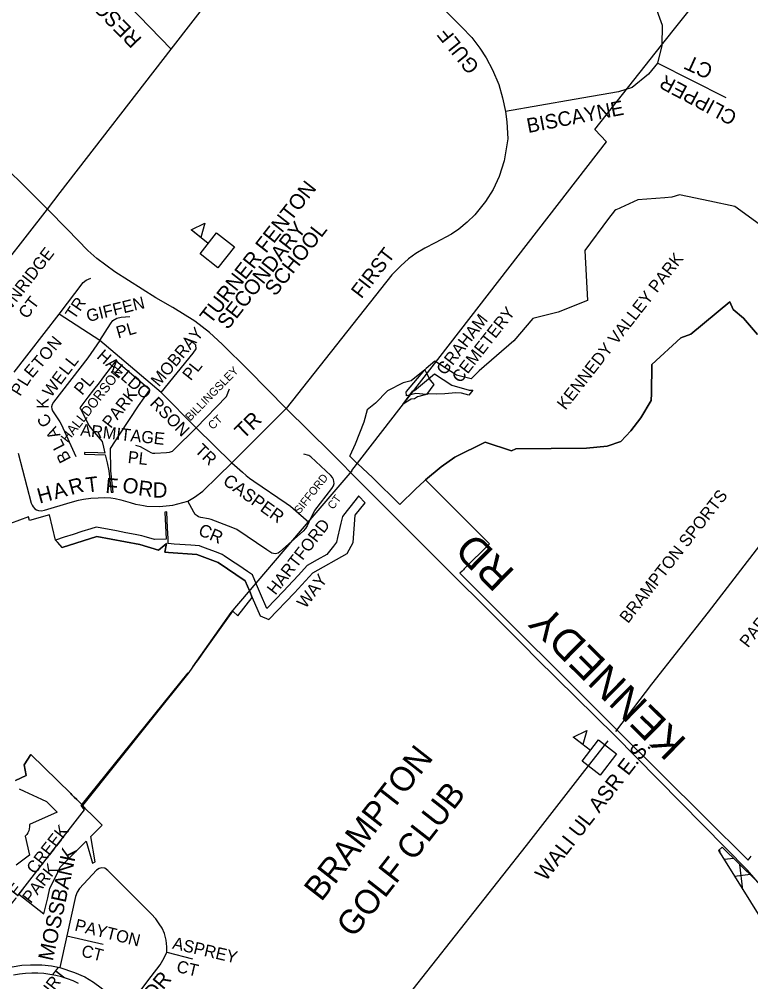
# Model space of a CAD drawing. Extents: x 586326 to 623965, y 4819854 to 4857850.
# Drawn here: x 602920 to 604127, y 4835364 to 4836952 of the extents above; entities that cross this region are included whole.
import ezdxf

# ---------------------------------------------------------------- set-up
doc = ezdxf.new("R2010")
doc.units = 0
for name, color, linetype in [('407 Parkway Belt', 7, 'Continuous'), ('Cemeteries', 7, 'Continuous'), ('Lots_Concessions', 7, 'Continuous'), ('Major Rds and Hwys', 7, 'Continuous'), ('Major Rds Lbls', 7, 'Continuous'), ('Minor Rd Lbls', 7, 'Continuous'), ('Minor Rds', 7, 'Continuous'), ('Park Lbls', 7, 'Continuous'), ('Park Outlines', 7, 'Continuous'), ('Proposed Secondary Rds', 7, 'Continuous'), ('Pts of Interest', 7, 'Continuous'), ('School Syms_Lbls', 7, 'Continuous')]:
    doc.layers.add(name, color=color, linetype=linetype)

msp = doc.modelspace()

# ---------------------------------------------------------------- linework, layer by layer
at = {"layer": '407 Parkway Belt'}
for p, q in [((604076.8, 4835576.2), (604076, 4835582.9)), ((604099.2, 4835568), (604083.2, 4835566)), ((604114.4, 4835516.1), (604109.2, 4835558.1)), ((604126.6, 4835541.1), (604100.7, 4835537.9))]:
    msp.add_line(p, q, dxfattribs=at)
msp.add_lwpolyline([(604440.3, 4835233.5), (604080.2, 4835586.6), (604073.8, 4835581), (604206.1, 4835369.5), (604182.1, 4835313.5)], dxfattribs=at)
at = {"layer": 'Cemeteries'}
for p, q in [((603572.2, 4836339.7), (603605.2, 4836367)), ((603605.2, 4836367), (603633.8, 4836348.7)), ((603633.8, 4836348.7), (603662.4, 4836340.4)), ((603552.9, 4836316.5), (603569.6, 4836339)), ((603566.7, 4836325.5), (603561.3, 4836322)), ((603572.2, 4836326.2), (603566.7, 4836325.5)), ((603569.6, 4836339), (603572.2, 4836339.7)), ((603577.3, 4836329.4), (603572.2, 4836326.2)), ((603595.9, 4836334.2), (603577.3, 4836329.4)), ((603608.4, 4836333.9), (603595.9, 4836334.2)), ((603622.5, 4836334.5), (603608.4, 4836333.9)), ((603640.8, 4836336.1), (603622.5, 4836334.5)), ((603649.8, 4836335.5), (603640.8, 4836336.1)), ((603661.9, 4836332.3), (603649.8, 4836335.5)), ((603668.6, 4836340.3), (603661.9, 4836332.3)), ((603662.4, 4836340.4), (603668.6, 4836340.3)), ((603561.3, 4836322), (603552.9, 4836316.5))]:
    msp.add_line(p, q, dxfattribs=at)
at = {"layer": 'Lots_Concessions'}
for p, q in [((603980, 4836909.2), (604121.5, 4837088.4)), ((603870.1, 4836770.5), (603980, 4836909.2)), ((603889.4, 4836749.9), (603870.1, 4836770.5)), ((603468.9, 4836207.8), (603889.4, 4836749.9)), ((603400.4, 4836126.6), (603469.6, 4836207)), ((603269.7, 4835973.6), (603400.4, 4836126.6)), ((604057.3, 4835974.1), (604147.8, 4836091.2)), ((603206.8, 4835884.2), (603269.7, 4835973.6)), ((603964.3, 4835855.3), (604057.3, 4835974.1)), ((603022.1, 4835655), (603199.1, 4835874.3)), ((603904.4, 4835777.3), (603964.3, 4835855.3)), ((603891.6, 4835761.9), (603852.8, 4835712.7)), ((603852.8, 4835712.7), (603756.4, 4835589.2)), ((602918.1, 4835507.5), (603028, 4835648.2)), ((603028, 4835648.2), (603022.1, 4835655)), ((603756.4, 4835589.2), (603561.5, 4835341.6))]:
    msp.add_line(p, q, dxfattribs=at)
at = {"layer": 'Major Rds and Hwys'}
for points in [[(603170.9, 4836903.1), (603308.5, 4837080.7)], [(603527.1, 4837063.6), (603650, 4836939.9), (603666.9, 4836922.3), (603680, 4836904.6), (603690.7, 4836888.4), (603701.2, 4836868.9), (603711.5, 4836844.6), (603717.8, 4836822.3), (603722.8, 4836799.8)], [(602966.9, 4836638.8), (602987.5, 4836666.2), (603170.9, 4836903.1)], [(603722.8, 4836799.8), (603725, 4836782.9), (603726.5, 4836754.8), (603720.4, 4836718.4), (603712.1, 4836692.7), (603702.2, 4836671.1), (603689.8, 4836651.3), (603672.1, 4836629.7), (603659.2, 4836617.4), (603645.5, 4836606.1), (603633.2, 4836597.9), (603606.6, 4836583.3), (603589.6, 4836574.7), (603574.6, 4836566), (603562.7, 4836556.8), (603549.8, 4836545.2), (603535, 4836530.4), (603360.8, 4836310.3)], [(602861, 4836743.4), (602966.9, 4836638.8)], [(602760.5, 4836375), (602966.9, 4836638.8)], [(603360.8, 4836310.3), (603298.4, 4836373.3), (603255, 4836416.3), (603234.2, 4836435.7), (603209.6, 4836454.2), (603173.3, 4836476.8), (603145.6, 4836492.8), (603077.6, 4836535.5), (603048.1, 4836557.4), (603033.4, 4836570.8), (602999.8, 4836605.4), (602966.9, 4836638.8)], [(603774.3, 4835897.3), (603752.3, 4835919.6), (603575.3, 4836096.2), (603484.8, 4836186.6), (603434.8, 4836237.2), (603360.8, 4836310.3)], [(604337.6, 4835278.9), (604308.1, 4835309.2), (604277.8, 4835343.1), (604258.5, 4835367.1), (604192.7, 4835460.5), (604158.3, 4835506.7), (604146.1, 4835520.7), (604121.9, 4835548.7), (603938.1, 4835734.8), (603902.8, 4835770.5), (603774.3, 4835897.3)]]:
    msp.add_lwpolyline(points, dxfattribs=at)
at = {"layer": 'Minor Rds'}
for points in [[(603170.9, 4836903.1), (603013.2, 4837065.9), (602999.7, 4837080.1), (602982.3, 4837098.9), (602979.3, 4837102.7), (602977.5, 4837106.4), (602976.5, 4837110.3), (602976.2, 4837114.7), (602977.4, 4837121.1), (602979.6, 4837126.5), (602982.2, 4837130.7), (603029.8, 4837199.6), (603037.7, 4837209), (603044, 4837215.9), (603108.5, 4837280.6)], [(603527.1, 4837063.6), (603666.3, 4837221.6), (603689.3, 4837242.9), (603721.9, 4837257.7), (603743.4, 4837261.2), (603765.2, 4837262.1), (603785.9, 4837258.3), (603806.6, 4837251.9), (603834.5, 4837234.7), (603851.1, 4837217.8), (603871.2, 4837185.8), (603885.2, 4837162.5), (603904.7, 4837130.5), (603918.6, 4837101.1), (603965.2, 4836987), (603980.9, 4836942.2), (603980.6, 4836908.7), (603973.6, 4836879.9)], [(603973.6, 4836879.9), (603958.5, 4836861.6), (603931.7, 4836839.8), (603909, 4836832.5), (603835.6, 4836819.6), (603722.8, 4836799.8)], [(604086.9, 4836822.3), (603973.6, 4836879.9)], [(602986, 4836465.9), (603025.4, 4836517.7), (603030.3, 4836521.8), (603038.2, 4836525.3)], [(602911.6, 4836369.9), (602986, 4836465.9)], [(603053.3, 4836422.5), (602986, 4836465.9)], [(603053.3, 4836422.5), (603070.5, 4836449.9), (603074.6, 4836455.3), (603080.9, 4836459), (603088.3, 4836460.9), (603102.5, 4836462.1)], [(603053.3, 4836422.5), (603033.4, 4836393.6), (602976.7, 4836320.4), (602974.5, 4836316.4), (602973.2, 4836312.7), (602973.6, 4836309.3), (602975.1, 4836306.4), (602986.9, 4836288.2), (602989.4, 4836284), (603013.6, 4836231.1)], [(603154.1, 4836336.6), (603053.3, 4836422.5)], [(603154.1, 4836336.6), (603207.2, 4836401.3), (603211.8, 4836408.7), (603211.6, 4836414.6), (603205.2, 4836420.3), (603191.9, 4836426.3)], [(603212.2, 4836278.2), (603262, 4836329.7), (603267.1, 4836342.5)], [(603212.2, 4836278.2), (603154.1, 4836336.6)], [(603270.8, 4836220.5), (603360.8, 4836310.3)], [(603212.2, 4836278.2), (603176, 4836242.3), (603172.4, 4836239.4), (603167.6, 4836237.3), (603163.3, 4836236.9), (603144.1, 4836235.6), (603140.8, 4836235.9), (603137.6, 4836236.8), (603134, 4836239.2), (603120.3, 4836247.1), (603112.3, 4836249.3)], [(603270.8, 4836220.5), (603212.2, 4836278.2)], [(602918.4, 4836236.4), (602940, 4836153.7), (602941.5, 4836150.5), (602943.3, 4836147.7), (602946, 4836144.8), (602948.7, 4836142.9), (602952.1, 4836141.7), (602956.7, 4836141.5), (602961.9, 4836142.3), (603004, 4836155.2), (603018.1, 4836158.7), (603026.4, 4836160.3), (603038.3, 4836162.2), (603050.4, 4836162.8), (603060.2, 4836163.2), (603071.5, 4836162.7), (603078.5, 4836161.6), (603087.7, 4836159.4), (603102.9, 4836155), (603111.7, 4836152.5), (603119.1, 4836150.9), (603125.3, 4836149.9), (603130.6, 4836149.1), (603151.6, 4836148.5), (603173.5, 4836150.5), (603198.1, 4836157.3)], [(603397.9, 4836122.6), (603407.8, 4836141.8), (603435.7, 4836178.3), (603438.9, 4836182.7), (603439.7, 4836186.1), (603439.3, 4836189.5), (603438.8, 4836193), (603437, 4836196.1), (603434.4, 4836199.3), (603401.3, 4836230.2), (603397.9, 4836232.4), (603389.8, 4836235)], [(603198.1, 4836157.3), (603209.4, 4836163.7), (603223.3, 4836173.9), (603247.8, 4836197.9), (603270.8, 4836220.5)], [(603270.8, 4836220.5), (603288.3, 4836205), (603294.5, 4836199.6), (603299.9, 4836195.4), (603307.3, 4836190.3), (603360.7, 4836153.9), (603367.6, 4836149.1), (603372.4, 4836145.2), (603397.9, 4836122.6)], [(603397.9, 4836122.6), (603395.2, 4836116.3), (603392.7, 4836111.9), (603388.9, 4836107.7), (603350.2, 4836073.6), (603347.2, 4836071.7), (603345, 4836070.9), (603342.3, 4836070.6), (603339.9, 4836070.7), (603336.8, 4836071.6), (603328.7, 4836076.9), (603279.1, 4836110.2), (603272.7, 4836113.3), (603236.9, 4836126.9), (603232.3, 4836128.2), (603219.5, 4836130.3), (603216.1, 4836131.2), (603213.5, 4836132.8), (603210.5, 4836135.3), (603208.2, 4836139), (603198.1, 4836157.3)], [(603163.5, 4835413), (603163.9, 4835422), (603162.4, 4835432.9), (603159.6, 4835443.8), (603155.8, 4835453.1), (603151.1, 4835460.2), (603145.3, 4835468.4), (603137.9, 4835476.5), (603066.5, 4835547.9), (603061.5, 4835551.6), (603056.5, 4835552.6), (603052.1, 4835551.5), (603047.7, 4835548.4), (603019.3, 4835518.1), (603015.8, 4835512.1), (603013.2, 4835504.9), (602998.9, 4835440.4)], [(602998.9, 4835440.4), (602987.2, 4835387.9)], [(602998.9, 4835440.4), (603058.4, 4835426.3)], [(603097.5, 4835319.5), (603137.9, 4835372.9), (603152.4, 4835392.4), (603159.5, 4835403.8), (603163.5, 4835413)], [(603163.5, 4835413), (603205.9, 4835402.1)]]:
    msp.add_lwpolyline(points, dxfattribs=at)
at = {"layer": 'Park Outlines'}
for points in [[(604147.1, 4836609.8), (604101.2, 4836643.1), (604059.6, 4836652.1), (604009.7, 4836662.8), (603997, 4836658.6), (603985.7, 4836657.7), (603940.9, 4836654.3), (603912.2, 4836641), (603909.9, 4836640), (603904.9, 4836637.6), (603902.2, 4836636.4), (603892.7, 4836623.6), (603853.5, 4836570.8), (603857.6, 4836488), (603809.5, 4836469.1), (603767.5, 4836458.3), (603736.3, 4836421.8), (603679.1, 4836372.1), (603665.8, 4836359.2), (603641.8, 4836365.1), (603606, 4836387.9), (603591.8, 4836376.2), (603589.2, 4836374.1), (603591.1, 4836370.5), (603598, 4836357), (603604.1, 4836349.4), (603592.2, 4836333.2), (603574.6, 4836334.6), (603558.9, 4836330.9), (603558.7, 4836337.7), (603559, 4836338.1), (603589.2, 4836374.1), (603567.1, 4836355.8), (603553.4, 4836352.4), (603528, 4836339.1), (603508, 4836319.1), (603494.2, 4836308.1), (603488.6, 4836287.3), (603474.3, 4836251.5), (603465.4, 4836232.2), (603465.3, 4836231.9), (603476.8, 4836220.5), (603478.2, 4836219.1), (603503.7, 4836195.8), (603547.9, 4836151.7), (603574.3, 4836176.8), (603589.1, 4836190.8), (603590.6, 4836192.3), (603616.2, 4836214), (603639.2, 4836229.6), (603689, 4836254.8), (603732.7, 4836240.4), (603739.4, 4836243.4), (603856.1, 4836244.7), (603890.4, 4836248), (603912.7, 4836255.5), (603929.6, 4836273.5), (603946.1, 4836294.7), (603962.8, 4836323), (603963.4, 4836334.8), (603964.2, 4836382.4), (604012, 4836426.4), (604028.4, 4836432.5), (604092.9, 4836486.2), (604098, 4836473.2), (604115.4, 4836459.2), (604138.5, 4836432.4)], [(604138.5, 4836432.4), (604115.4, 4836459.2), (604098, 4836473.2), (604092.9, 4836486.2), (604028.4, 4836432.5), (604012, 4836426.4), (603964.2, 4836382.4), (603963.4, 4836334.8), (603962.8, 4836323), (603946.1, 4836294.7), (603929.6, 4836273.5), (603912.7, 4836255.5), (603890.4, 4836248), (603856.1, 4836244.7), (603739.4, 4836243.4), (603732.7, 4836240.4), (603689, 4836254.8), (603639.2, 4836229.6), (603616.2, 4836214), (603590.6, 4836192.3), (603695.9, 4836087), (603654.5, 4836045.6), (603653.1, 4836044.2), (603653, 4836044.1), (603650.9, 4836042), (603647.4, 4836038.5), (603906.9, 4835779.4), (604052, 4835635.5), (604122.9, 4835565), (604128, 4835571.5)], [(602913.7, 4835696.3), (602931.5, 4835704.6), (602928, 4835722.1), (602939.4, 4835739.5), (603005.1, 4835674.9), (603007.1, 4835672.9), (603011, 4835669.1), (603014.9, 4835665.3), (603017.9, 4835662.4), (603025, 4835655.3), (603138.3, 4835796.8), (603200.6, 4835874.7), (603210.6, 4835888.8), (603212.2, 4835891.1), (603214.2, 4835893.8), (603216, 4835896.3), (603226, 4835910.5), (603272.6, 4835976), (603280.9, 4835968.2), (603304.6, 4835998.4), (603300.4, 4836008.4), (603293, 4836025.6), (603248.1, 4836056), (603213, 4836069.1), (603166.6, 4836072.6), (603160.2, 4836073.1), (603163, 4836087.5), (603159.1, 4836084.3), (603149.7, 4836076.4), (603119, 4836085.6), (603047.9, 4836099.1), (602991.2, 4836080.9), (602983.8, 4836088.9), (602980, 4836093), (602970.1, 4836134.8), (602937, 4836125.4), (602935.5, 4836131.2), (602905.5, 4836120.4)], [(602919.5, 4835508.8), (602960.8, 4835476.3), (602963.9, 4835489.7), (602967, 4835503), (602970.7, 4835518.8), (602979.2, 4835536.1), (602987.8, 4835553.7), (602999.3, 4835565.2), (603009, 4835574.9), (603030.5, 4835596.5), (603040.9, 4835560), (603043.1, 4835561.4), (603045.5, 4835562.5), (603038.2, 4835604.2), (603056.9, 4835622.7), (603041, 4835638.5), (603030.2, 4835649.3), (603025, 4835655.3), (603017.9, 4835662.4), (603014.9, 4835665.3), (603011, 4835669.1), (603007.1, 4835672.9), (603005.1, 4835674.9), (602939.4, 4835739.5), (602928, 4835722.1), (602931.5, 4835704.6), (602913.7, 4835696.3)], [(602920.1, 4835682.7), (602928.2, 4835679), (602956.9, 4835665.7), (602964.8, 4835662), (602982.5, 4835644.3), (602936.8, 4835623.6), (602937, 4835620.1), (602936.7, 4835616.7), (602935.8, 4835613.3), (602934.4, 4835610.1), (602932.5, 4835607.3), (602930.1, 4835604.8), (602937, 4835573.4), (602914.9, 4835556.6)], [(603018, 4835361.8), (603008.9, 4835365.9), (602999.5, 4835369.4), (602990, 4835372.4), (602980.3, 4835374.8), (602970.5, 4835376.6), (602960.6, 4835377.9), (602950.6, 4835378.5), (602940.6, 4835378.6), (602930.6, 4835378.1), (602920.7, 4835377), (602910.8, 4835375.3)]]:
    msp.add_lwpolyline(points, dxfattribs=at)
for points in [[(603068.1, 4836207.5), (603072, 4836172.3), (603073.4, 4836172.1), (603075, 4836171.9), (603071.2, 4836207.2), (603070.6, 4836243.9), (603086.1, 4836267.6), (603116.8, 4836314.2), (603135.4, 4836340.9), (603079.3, 4836388.6), (603070.1, 4836376.5), (603060.9, 4836364.6), (603051.8, 4836352.6), (603042.6, 4836340.6), (603033.5, 4836328.7), (603020.3, 4836311.3), (603021.4, 4836309.6), (603023.1, 4836306.2), (603028.7, 4836294.7), (603034.9, 4836282.1), (603043.8, 4836271.2), (603056.7, 4836255.4), (603058.9, 4836246.2), (603061.2, 4836236.6), (603049.8, 4836236.9), (603027.9, 4836237.7), (603028, 4836236.2), (603028, 4836234.7), (603061.9, 4836233.5), (603062.4, 4836231.4), (603065, 4836220.5)], [(603163, 4836087.5), (603160.2, 4836073.1), (603166.6, 4836072.6), (603213, 4836069.1), (603248.1, 4836056), (603293, 4836025.6), (603300.4, 4836008.4), (603304.6, 4835998.4), (603317.9, 4835967.8), (603332.2, 4835961.8), (603374.3, 4836006), (603404.7, 4836039.1), (603461, 4836071), (603471.1, 4836089.2), (603474.2, 4836133.9), (603491, 4836154.7), (603480.3, 4836165.4), (603480.1, 4836165.2), (603471.8, 4836154.8), (603471.3, 4836154.2), (603470.3, 4836152.9), (603461.3, 4836141.8), (603453.5, 4836132.1), (603453, 4836129.8), (603450.9, 4836121.1), (603449.2, 4836113.5), (603445.3, 4836097.1), (603443.6, 4836089.4), (603438.6, 4836083.2), (603427.7, 4836069.4), (603412, 4836060.5), (603395.3, 4836051), (603380.7, 4836035.2), (603363.3, 4836016.2), (603356.6, 4836009.1), (603328.9, 4835980.1), (603318.5, 4836004.2), (603315.2, 4836011.8), (603308.9, 4836026.6), (603305.1, 4836035.6), (603296.8, 4836041.1), (603282.4, 4836050.9), (603270.4, 4836059), (603258.5, 4836067), (603255.1, 4836069.3), (603245.4, 4836072.9), (603232, 4836077.9), (603218.5, 4836083), (603217.5, 4836083.3), (603203.2, 4836084.4), (603176, 4836086.5), (603166, 4836087.3), (603165.6, 4836095), (603164.8, 4836113.3), (603163.6, 4836139.2), (603163.7, 4836139.5), (603160.6, 4836139.2), (603162.6, 4836094.8), (603143.2, 4836093.9), (603126.4, 4836098.9), (603122.6, 4836100.1), (603111.2, 4836102.2), (603096, 4836105.1), (603080.8, 4836108), (603065.6, 4836110.9), (603050.3, 4836113.8), (603047, 4836114.4), (603038.1, 4836111.6), (603023.6, 4836106.9), (603009, 4836102.3), (602994.5, 4836097.6), (602980, 4836093), (602980, 4836093), (602980, 4836093), (602991.2, 4836080.9), (602991.2, 4836080.9), (603047.9, 4836099.1), (603119, 4836085.6), (603149.7, 4836076.4), (603159.1, 4836084.3)]]:
    msp.add_lwpolyline(points, close=True, dxfattribs=at)
at = {"layer": 'Proposed Secondary Rds'}
for points in [[(602875.6, 4835379.5), (602889.5, 4835384.4), (602908.3, 4835389), (602924.4, 4835391.7), (602938.9, 4835392.4), (602957.6, 4835392.6), (602973.3, 4835390.7), (602987.2, 4835387.9)], [(602987.2, 4835387.9), (603011.5, 4835379.9), (603028.3, 4835372.3), (603042.5, 4835363.5), (603055.3, 4835354.6), (603097.5, 4835319.5)]]:
    msp.add_lwpolyline(points, dxfattribs=at)
at = {"layer": 'School Syms_Lbls'}
for p, q in [((603232.1, 4836582.5), (603203.6, 4836604.7)), ((603862.6, 4835745.9), (603834.2, 4835768.1))]:
    msp.add_line(p, q, dxfattribs=at)
for points in [[(603203.6, 4836604.7), (603226.4, 4836615.7), (603219.5, 4836592.2)], [(603218.4, 4836565), (603245.7, 4836599.9), (603275.3, 4836576.8), (603248, 4836541.9)], [(603834.2, 4835768.1), (603857, 4835779.1), (603850.1, 4835755.6)], [(603849, 4835728.4), (603876.2, 4835763.3), (603905.8, 4835740.2), (603878.6, 4835705.3)]]:
    msp.add_lwpolyline(points, close=True, dxfattribs=at)

# ---------------------------------------------------------------- texts
at = {"layer": 'Cemeteries'}
for s, p in [('CEMETERY', (603648.1, 4836350.7)), ('GRAHAM', (603622.4, 4836363.5))]:
    msp.add_text(s, height=20, rotation=52, dxfattribs=at).set_placement(p)
at = {"layer": 'Major Rds Lbls'}
for s, height, rotation, p in [('GULF', 24, 128.7844, (603680.6, 4836874.2)), ('FIRST', 24, 52.2863, (603484.7, 4836490)), ('KENNEDY    RD ', 49.998, 135.54, (604023.5, 4835762.2))]:
    msp.add_text(s, height=height, rotation=rotation, dxfattribs=at).set_placement(p)
at = {"layer": 'Minor Rd Lbls'}
for s, height, rotation, p in [('RESOLUTION', 25, 134.1829, (603123.7, 4836919.9)), ('CT', 25, 155.3119, (604067.1, 4836875)), ('CLIPPER', 24, 152.0423, (604106.6, 4836797.1)), ('BISCAYNE', 24, 10.8855, (603760, 4836764.4)), ('BROWNRIDGE', 20, 52.1301, (602864, 4836418.1)), ('CT', 20, 53.0051, (602932.9, 4836456.7)), ('TR', 20, 55.7949, (603011.1, 4836455.5)), ('GIFFEN', 20, 13.7316, (603033.5, 4836452.6)), ('PL', 20, 15.8011, (603083.3, 4836425.4)), ('MOBRAY', 20, 49.7823, (603150.5, 4836344.7)), ('N', 20, 50.1944, (602979.5, 4836404.1)), ('O', 20, 50.1944, (602965.5, 4836387.1)), ('HALLDO', 20, 319.0473, (603046.7, 4836394.2)), ('T', 20, 50.1944, (602954.5, 4836374.1)), ('L', 20, 51.4635, (603010.1, 4836377.3)), ('E', 20, 50.1944, (602941.5, 4836359.1)), ('L', 20, 52.1876, (602999.9, 4836363.6)), ('PL', 20, 51.5242, (603203.2, 4836354.7)), ('BILLINGSLEY', 13.53, 45.6903, (603202.2, 4836288.4)), ('L', 20, 58.134, (602932.5, 4836345.1)), ('W', 20, 52.9759, (602972.6, 4836327.2)), ('E', 20, 53.0456, (602988.2, 4836347.7)), ('PL', 20, 50.1364, (603023.9, 4836330.7)), ('P', 20, 58.134, (602921.5, 4836329.1)), ('K', 20, 90, (602968.7, 4836309.6)), ('RSON', 20, 314.7002, (603134.5, 4836317.2)), ('C', 20, 126.0274, (602975.5, 4836288.1)), ('CT', 13.53, 43.0374, (603239.2, 4836274.4)), ('TR', 25, 44.256, (603290.4, 4836258.3)), ('A', 20, 117.582, (602988.5, 4836266.1)), ('ARMITAGE', 20, 353.6598, (603020.2, 4836265.3)), ('L', 20, 117.582, (602996, 4836247.8)), ('TR', 20, 315.971, (603208.7, 4836239.5)), ('B', 20, 117.582, (603006, 4836226.8)), ('PL', 20, 353.6598, (603098.5, 4836220.3)), ('T', 25, 7.125, (603031.5, 4836171.2)), ('CASPER', 20.85, 324.1928, (603254.6, 4836186.7)), ('SIFFORD', 13.17, 51.582, (603382.6, 4836135.1)), ('H', 25, 15.2551, (602953.5, 4836153.1)), ('A', 25, 15.2551, (602979.5, 4836160.1)), ('R', 25, 15.2551, (603005.5, 4836167.1)), ('F', 25, 354.8056, (603061.6, 4836170.9)), ('O', 25, 347.7996, (603088.5, 4836173.1)), ('R', 25, 352.875, (603115.5, 4836167.1)), ('D', 25, 0, (603140.5, 4836163.1)), ('CT', 13.17, 53.1301, (603438.2, 4836142.6)), ('CR', 20.76, 336.5713, (603213.9, 4836102.1)), ('MOSSBANK', 25, 77.692, (602975.4, 4835397.6)), ('PAYTON', 20, 345.9638, (603010.3, 4835449.1)), ('ASPREY', 20, 346.8094, (603171.7, 4835419.3)), ('CT', 20, 345.9638, (603021.2, 4835406.5)), ('CT', 20, 346.8094, (603178.4, 4835380.8)), ('DR', 25, 50.371, (603142.1, 4835331.3))]:
    msp.add_text(s, height=height, rotation=rotation, dxfattribs=at).set_placement(p)
at = {"layer": 'Park Lbls'}
for s, height, p in [('KENNEDY VALLEY PARK', 19.992, (603821.5, 4836306.4)), ('HALLDORSON', 16.28, (602999.9, 4836252.6)), ('PARK', 19.99, (603071.1, 4836276.1)), ('BRAMPTON SPORTS', 19.992, (603924.7, 4835954.4)), ('HARTFORD', 19.99, (603342.8, 4836001.1)), ('WAY', 19.99, (603392.3, 4835978.9)), ('PARK', 19.99, (604122.8, 4835914.3)), ('TURTLE    CREEK', 19.992, (602863.6, 4835435.3)), ('PARK', 19.99, (602939.2, 4835492.4)), ('COUNTY COURT', 19.992, (602867.4, 4835207.5))]:
    msp.add_text(s, height=height, rotation=52, dxfattribs=at).set_placement(p)
at = {"layer": 'Pts of Interest'}
for s, p in [('BRAMPTON', (603418.5, 4835495.1)), ('GOLF CLUB', (603471.9, 4835435.2))]:
    msp.add_text(s, height=39.98, rotation=52, dxfattribs=at).set_placement(p)
at = {"layer": 'School Syms_Lbls'}
for s, p in [('TURNER FENTON', (603235.8, 4836447.8)), ('SECONDARY', (603264.3, 4836438.8)), ('SCHOOL', (603342.7, 4836494)), ('WALI UL ASR E.S.', (603788.9, 4835528.8))]:
    msp.add_text(s, height=25, rotation=52, dxfattribs=at).set_placement(p)

doc.saveas('drawing.dxf')
